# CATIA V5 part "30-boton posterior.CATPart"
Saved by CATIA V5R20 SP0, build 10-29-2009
Part number: 30-boton posterior
Revision: ANY
Definition: UNKNOWN
Nomenclature: 30-boton posterior
Source: Unknown
Bounding box of the stored display mesh (mm): x -2.8 to 2.8, y 0 to 8.6, z -3.5 to 3.5
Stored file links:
  C:\Users\Utente\Desktop\IO LAVORO\3D X SITO CF\CUMSA\3D files CC\CCHS5328\30-boton posterior.CATPart
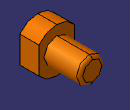
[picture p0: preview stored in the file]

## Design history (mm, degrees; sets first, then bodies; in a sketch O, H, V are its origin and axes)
Body1 "Redondeo1" (main body)
  Solid1: solid without history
